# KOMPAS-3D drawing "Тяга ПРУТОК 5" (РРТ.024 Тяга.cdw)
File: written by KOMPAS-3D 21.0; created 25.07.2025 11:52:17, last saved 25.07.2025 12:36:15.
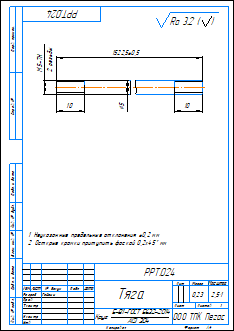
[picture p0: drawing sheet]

Sheet 1: A4, portrait

Document properties: Автор: User; Знак неуказанной шероховатости: 4; Параметр неуказанной шероховатости: Ra 3.2; Масса: 0.234849

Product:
- Part/product: Тяга ПРУТОК 5
    Масса: 0.234849
    Форматы листов документа: A4

Title block, sheet 1: Наименование: Тяга; designation: РРТ.024; Материал: Круг  5-B1-ГОСТ 5632-2014 AISI 304; Масса: 0,23; Количество листов документа: 1; organisation: ООО ТПК Пегас; Форматы листов документа: A4; stored path: C:\Users\User\Desktop\Ручной ротатор КД\Чертежи\РРТ.024 Тяга.cdw; Разработал: Гайсин

Views: Вид 1, Спереди
Referenced files in C:\Users\User\Desktop\Ручной ротатор КД\Модели КД\: РРТ.024 Тяга.m3d
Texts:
  Тяга ПРУТОК 5
  Ra 3.2
  Ra 3.2 ( )
Dimensions and other numbers on the sheet: 1522,5±0,5; -7Н; 2 резьбы; 10; 5; 2,5:1; 1; 0,23

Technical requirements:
  Неуказанные предельные отклонения  0,2 мм
  Осткрые кромки притупить фаской 0,2х45  мм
